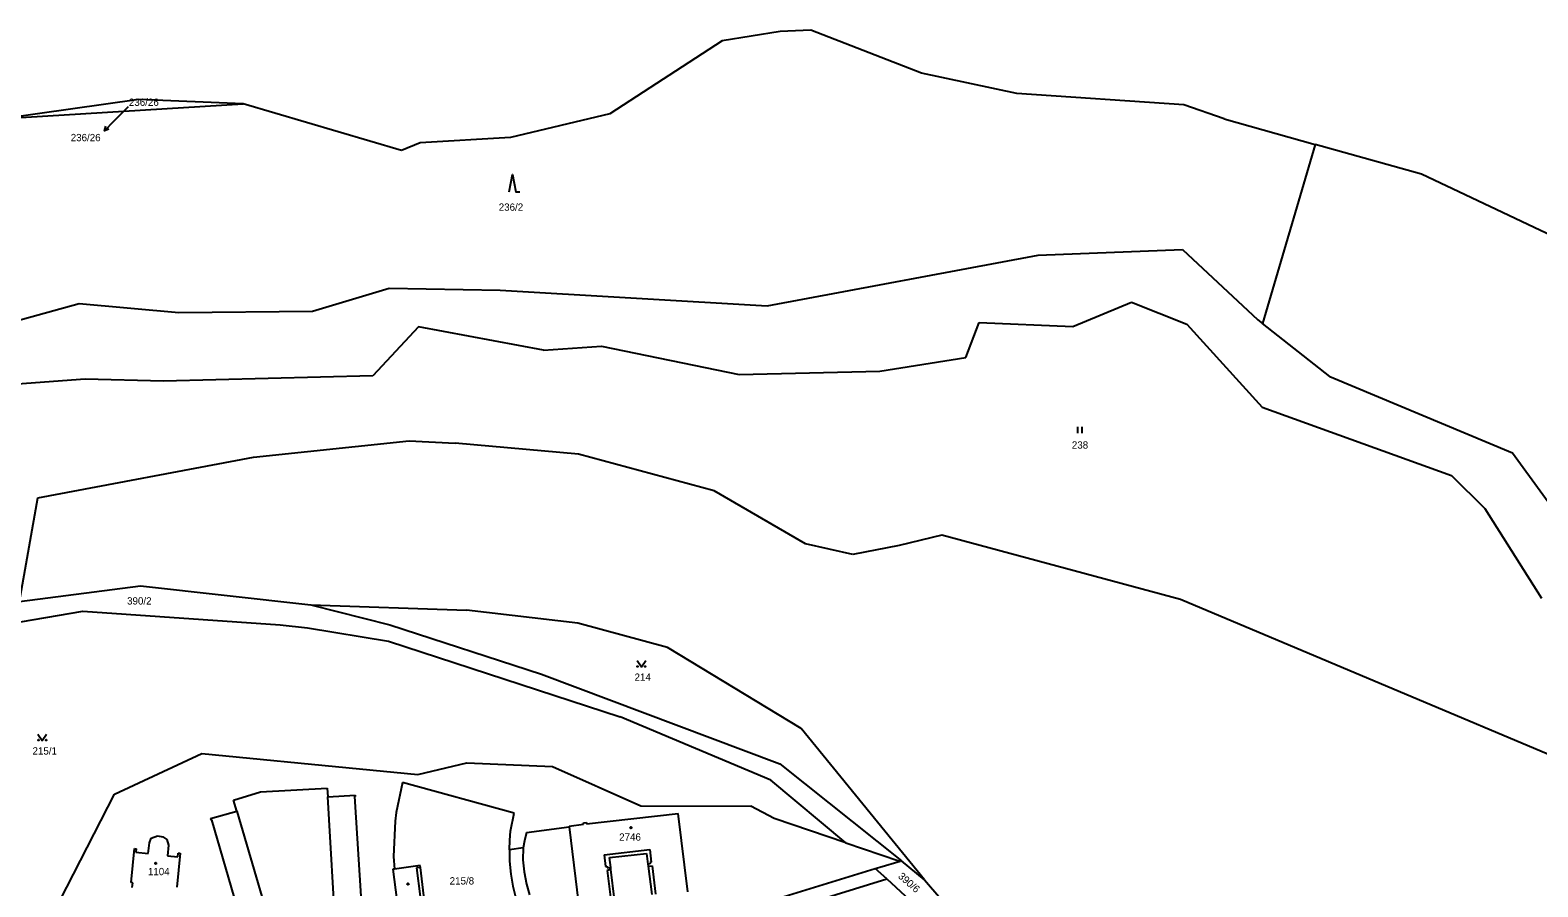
# Model space of a CAD drawing. Extents: x -735249 to -729401, y -1124843 to -1121828.
# Drawn here: x -733183.2 to -732832.6, y -1123120 to -1122920.8 of the extents above; entities that cross this region are included whole.
import ezdxf

# ---------------------------------------------------------------- set-up
doc = ezdxf.new("R2010")
doc.units = 0
for name, color, linetype in [('Vrstva 1', 7, 'Continuous'), ('Vrstva 13', 7, 'Continuous'), ('Vrstva 16', 7, 'Continuous'), ('Vrstva 18', 7, 'Continuous'), ('Vrstva 19', 7, 'Continuous'), ('Vrstva 25', 7, 'Continuous'), ('Vrstva 4', 7, 'Continuous')]:
    doc.layers.add(name, color=color, linetype=linetype)

msp = doc.modelspace()

# ---------------------------------------------------------------- linework, layer by layer
at = {"layer": 'Vrstva 1'}
for points in [[(-733189.11, -1122941.34), (-733133.6, -1122937.93)], [(-732884.33, -1122947.37), (-732896.64, -1122989.01)], [(-732948.78, -1122973.13), (-732915.22, -1122971.84)], [(-732915.22, -1122971.84), (-732897.69, -1122988.19)], [(-733011.81, -1122984.95), (-732948.78, -1122973.13)], [(-733117.5, -1122986.15), (-733099.68, -1122980.84)], [(-733099.68, -1122980.84), (-733073.84, -1122981.26)], [(-733073.84, -1122981.26), (-733011.81, -1122984.95)], [(-733196.77, -1122991.3), (-733171.8, -1122984.4)], [(-733171.8, -1122984.4), (-733148.57, -1122986.49)], [(-733148.57, -1122986.49), (-733117.5, -1122986.15)], [(-732940.73, -1122989.73), (-732927.06, -1122984.09)], [(-732927.06, -1122984.09), (-732914.22, -1122989.21)], [(-733092.85, -1122989.79), (-733103.46, -1123001.22)], [(-733063.77, -1122995.26), (-733092.85, -1122989.79)], [(-732965.57, -1122996.96), (-732962.49, -1122988.81)], [(-732962.49, -1122988.81), (-732940.73, -1122989.73)], [(-732914.22, -1122989.21), (-732896.65, -1123008.47)], [(-732897.69, -1122988.19), (-732896.64, -1122989.01)], [(-732880.92, -1123001.36), (-732896.64, -1122989.01)], [(-733063.77, -1122995.26), (-733050.28, -1122994.29)], [(-733050.28, -1122994.29), (-733018.28, -1123000.89)], [(-732985.6, -1123000.09), (-732965.57, -1122996.96)], [(-733018.28, -1123000.89), (-732985.6, -1123000.09)], [(-733170.37, -1123001.95), (-733190.38, -1123003.43)], [(-733152.15, -1123002.42), (-733170.37, -1123001.95)], [(-733103.46, -1123001.22), (-733152.15, -1123002.42)], [(-732880.92, -1123001.36), (-732838.49, -1123019.06)], [(-732896.65, -1123008.47), (-732852.64, -1123024.38)], [(-733131.23, -1123020.12), (-733095.01, -1123016.34)], [(-733095.01, -1123016.34), (-733084.33, -1123016.85)], [(-733055.66, -1123019.42), (-733084.33, -1123016.85)], [(-733181.36, -1123029.55), (-733131.23, -1123020.12)], [(-733024.13, -1123027.9), (-733055.66, -1123019.42)], [(-732838.49, -1123019.06), (-732817.96, -1123047.33)], [(-732852.64, -1123024.38), (-732844.88, -1123032.05)], [(-733002.9, -1123040.26), (-733024.13, -1123027.9)], [(-733185.61, -1123053.69), (-733181.36, -1123029.55)], [(-732844.88, -1123032.05), (-732831.71, -1123052.91)], [(-732971.16, -1123038.2), (-732981.06, -1123040.67)], [(-732915.67, -1123053.17), (-732971.16, -1123038.2)], [(-732991.84, -1123042.7), (-733002.9, -1123040.26)], [(-732981.06, -1123040.67), (-732991.84, -1123042.7)], [(-733185.61, -1123053.69), (-733157.54, -1123050.02)], [(-733157.54, -1123050.02), (-733117.91, -1123054.44)], [(-732776.55, -1123111.77), (-732915.67, -1123053.17)], [(-733196.82, -1123060.33), (-733170.92, -1123055.92)], [(-733170.92, -1123055.92), (-733125, -1123059.07)], [(-733117.91, -1123054.44), (-733081.67, -1123055.68)], [(-733117.91, -1123054.44), (-733099.52, -1123059.12)], [(-733055.81, -1123058.66), (-733081.67, -1123055.68)], [(-733125, -1123059.07), (-733118.7, -1123059.82)], [(-733118.7, -1123059.82), (-733099.83, -1123062.89)], [(-733099.52, -1123059.12), (-733064.28, -1123070.55)], [(-733034.93, -1123064.35), (-733055.81, -1123058.66)], [(-733099.83, -1123062.89), (-733045.98, -1123080.5)], [(-733003.86, -1123083.15), (-733034.93, -1123064.35)], [(-733064.28, -1123070.55), (-733008.85, -1123091.44)], [(-733010.91, -1123095.2), (-733045.98, -1123080.5)], [(-732975.22, -1123118.38), (-733003.86, -1123083.15)], [(-733163.54, -1123098.49), (-733143.24, -1123088.98)], [(-733143.24, -1123088.98), (-733106.62, -1123092.53)], [(-733093.03, -1123093.89), (-733081.63, -1123091.2)], [(-733081.63, -1123091.2), (-733061.72, -1123092.03)], [(-733061.72, -1123092.03), (-733041.19, -1123101.14)], [(-733008.85, -1123091.44), (-732980.57, -1123113.98)], [(-733106.62, -1123092.53), (-733093.03, -1123093.89)], [(-732993.5, -1123109.8), (-733010.91, -1123095.2)], [(-733177.79, -1123126.27), (-733163.54, -1123098.49)], [(-733135.87, -1123099.84), (-733129.57, -1123097.94)], [(-733129.57, -1123097.94), (-733114.09, -1123097.06)], [(-733114.09, -1123097.06), (-733113.97, -1123099.06)], [(-733113.97, -1123099.06), (-733107.58, -1123098.68)], [(-733107.56, -1123098.98), (-733107.72, -1123098.99)], [(-733107.72, -1123098.99), (-733105.68, -1123131.95)], [(-733107.58, -1123098.68), (-733107.56, -1123098.98)], [(-733096.62, -1123095.71), (-733098.05, -1123102.75)], [(-733070.61, -1123102.85), (-733096.62, -1123095.71)], [(-733141.25, -1123104.12), (-733135.13, -1123102.38)], [(-733135.13, -1123102.38), (-733135.87, -1123099.84)], [(-733041.19, -1123101.14), (-733015.6, -1123101.24)], [(-733010.19, -1123104.15), (-733015.6, -1123101.24)], [(-733141.25, -1123104.12), (-733141.16, -1123104.43)], [(-733141.16, -1123104.43), (-733141.02, -1123104.39)], [(-733141.02, -1123104.39), (-733132.54, -1123133.48)], [(-733098.33, -1123104.72), (-733098.71, -1123112.94)], [(-733098.05, -1123102.75), (-733098.33, -1123104.72)], [(-733071.45, -1123107.08), (-733070.61, -1123102.85)], [(-733067.73, -1123107.33), (-733057.83, -1123106.07)], [(-733057.85, -1123105.86), (-733054.46, -1123105.44)], [(-733057.85, -1123105.86), (-733057.83, -1123106.07)], [(-733057.83, -1123106.07), (-733055.66, -1123123.85)], [(-733054.48, -1123105.13), (-733053.83, -1123105.08)], [(-733054.46, -1123105.44), (-733054.48, -1123105.13)], [(-733053.83, -1123105.08), (-733053.81, -1123105.39)], [(-733053.81, -1123105.39), (-733032.49, -1123102.93)], [(-733030.21, -1123121.19), (-733032.49, -1123102.93)], [(-732993.5, -1123109.8), (-733010.19, -1123104.15)], [(-733155.45, -1123109.75), (-733155.03, -1123108.69)], [(-733155.03, -1123108.69), (-733153.55, -1123108.12)], [(-733153.55, -1123108.12), (-733152.35, -1123108.36)], [(-733152.35, -1123108.36), (-733151.39, -1123109.03)], [(-733151.39, -1123109.03), (-733150.97, -1123110.31)], [(-733071.72, -1123111.4), (-733071.6, -1123109.15)], [(-733071.6, -1123109.15), (-733071.45, -1123107.08)], [(-733068.21, -1123109.28), (-733068.49, -1123110.95)], [(-733067.73, -1123107.33), (-733068.21, -1123109.28)], [(-733159.71, -1123119.03), (-733158.92, -1123111.09)], [(-733158.92, -1123111.09), (-733158.51, -1123111.14)], [(-733158.51, -1123111.14), (-733158.59, -1123111.92)], [(-733158.59, -1123111.92), (-733155.75, -1123112.23)], [(-733155.75, -1123112.23), (-733155.45, -1123109.75)], [(-733150.97, -1123110.31), (-733151.23, -1123112.76)], [(-733151.23, -1123112.76), (-733148.85, -1123113)], [(-733148.3, -1123112.17), (-733149.08, -1123120.11)], [(-733148.85, -1123113), (-733148.72, -1123112.21)], [(-733148.72, -1123112.21), (-733148.3, -1123112.17)], [(-733098.71, -1123112.94), (-733098.47, -1123115.87)], [(-733068.49, -1123110.95), (-733071.72, -1123111.4)], [(-733048.45, -1123113.21), (-733039.82, -1123112.24)], [(-733039.82, -1123112.24), (-733039.52, -1123114.71)], [(-732993.5, -1123109.8), (-732981.15, -1123113.99)], [(-733098.47, -1123115.87), (-733098.8, -1123115.93)], [(-733098.8, -1123115.93), (-733097.24, -1123128.54)], [(-733092.49, -1123115.01), (-733098.47, -1123115.87)], [(-733092.43, -1123115.48), (-733092.49, -1123115.01)], [(-733091.63, -1123122.07), (-733092.43, -1123115.48)], [(-733048.18, -1123115.51), (-733048.45, -1123113.21)], [(-733048.12, -1123116), (-733048.18, -1123115.51)], [(-733047.27, -1123122.96), (-733048.12, -1123116)], [(-733039.52, -1123114.71), (-733039.48, -1123115.19)], [(-733039.48, -1123115.19), (-733038.62, -1123121.77)], [(-733035.05, -1123130.65), (-732986.71, -1123115.74)], [(-732986.71, -1123115.74), (-732985.57, -1123115.4)], [(-732983.98, -1123118.16), (-732986.71, -1123115.74)], [(-732985.57, -1123115.4), (-732980.9, -1123114.07)], [(-732981.15, -1123113.99), (-732980.9, -1123114.07)], [(-732980.57, -1123113.98), (-732980.9, -1123114.07)], [(-732975.22, -1123118.38), (-732980.57, -1123113.98)], [(-733159.32, -1123119.07), (-733159.71, -1123119.03)], [(-733159.44, -1123120.18), (-733159.32, -1123119.07)], [(-733140.36, -1123166.52), (-732983.98, -1123118.16)], [(-732983.98, -1123118.16), (-732978.66, -1123123.04)], [(-732975.22, -1123118.38), (-732956.7, -1123139.95)]]:
    msp.add_lwpolyline(points, dxfattribs=at)
at = {"layer": 'Vrstva 13'}
for points in [[(-733022.26, -1122923.27), (-733048.34, -1122940.27)], [(-733008.79, -1122921.12), (-733022.26, -1122923.27)], [(-733001.61, -1122920.82), (-733008.79, -1122921.12)], [(-732975.9, -1122930.79), (-733001.61, -1122920.82)], [(-732953.74, -1122935.53), (-732975.9, -1122930.79)], [(-733157.87, -1122936.95), (-733189.11, -1122941.34)], [(-733133.6, -1122937.93), (-733157.87, -1122936.95)], [(-732914.88, -1122938.18), (-732953.74, -1122935.53)], [(-733096.81, -1122948.81), (-733133.6, -1122937.93)], [(-733048.34, -1122940.27), (-733071.46, -1122945.74)], [(-732905.5, -1122941.4), (-732914.88, -1122938.18)], [(-732905.5, -1122941.4), (-732884.33, -1122947.37)], [(-733092.47, -1122947), (-733096.81, -1122948.81)], [(-733071.46, -1122945.74), (-733092.47, -1122947)], [(-732859.61, -1122954.34), (-732884.33, -1122947.37)], [(-732794.28, -1122985.24), (-732859.61, -1122954.34)]]:
    msp.add_lwpolyline(points, dxfattribs=at)
at = {"layer": 'Vrstva 16'}
msp.add_lwpolyline([(-733160.41, -1122938.62), (-733163.8, -1122942.09)], dxfattribs=at)
at = {"layer": 'Vrstva 25'}
for points in [[(-733163.8, -1122942.09), (-733165.898, -1122944.233)], [(-733164.842, -1122943.868), (-733165.898, -1122944.233), (-733165.556, -1122943.169)], [(-733071.77, -1122958.41), (-733071.02, -1122954.41), (-733070.27, -1122958.41), (-733069.27, -1122958.41)], [(-732939.557, -1123014.545), (-732939.557, -1123013.045)], [(-732938.523, -1123014.545), (-732938.523, -1123013.045)], [(-733042.04, -1123067.36), (-733041.04, -1123068.86), (-733040.04, -1123067.36)], [(-733181.35, -1123084.47), (-733180.35, -1123085.97), (-733179.35, -1123084.47)]]:
    msp.add_lwpolyline(points, dxfattribs=at)
for centre, radius in [((-733041.94, -1123068.76), 0.1), ((-733040.14, -1123068.76), 0.1), ((-733181.25, -1123085.87), 0.1), ((-733179.45, -1123085.87), 0.1), ((-733043.48, -1123106.24), 0.175), ((-733153.96, -1123114.53), 0.175), ((-733095.31, -1123119.34), 0.175)]:
    msp.add_circle(centre, radius, dxfattribs=at)
at = {"layer": 'Vrstva 4'}
for points in [[(-733112, -1123132.26), (-733113.97, -1123099.06)], [(-733135.13, -1123102.38), (-733126.14, -1123133.12)], [(-733071.72, -1123111.4), (-733071.68, -1123114)], [(-733068.49, -1123110.95), (-733068.57, -1123113.69)], [(-733049.73, -1123112.53), (-733039.06, -1123111.29)], [(-733049.73, -1123112.53), (-733049.41, -1123115.26)], [(-733039.06, -1123111.29), (-733038.74, -1123114.29)], [(-733092.43, -1123115.48), (-733093.33, -1123115.62)], [(-733093.33, -1123115.62), (-733092.47, -1123122.25)], [(-733071.68, -1123114), (-733071.42, -1123117.08)], [(-733068.57, -1123113.69), (-733068.26, -1123116.54)], [(-733068.26, -1123116.54), (-733067.75, -1123119.37)], [(-733049.41, -1123115.26), (-733049.03, -1123115.22)], [(-733049.03, -1123115.22), (-733048.98, -1123115.61)], [(-733048.98, -1123115.61), (-733048.18, -1123115.51)], [(-733048.12, -1123116), (-733048.98, -1123116.19)], [(-733048.98, -1123116.19), (-733048.14, -1123123.06)], [(-733039.02, -1123114.65), (-733039.52, -1123114.71)], [(-733039.48, -1123115.19), (-733038.57, -1123115.1)], [(-733038.74, -1123114.29), (-733039.06, -1123114.33)], [(-733039.06, -1123114.33), (-733039.02, -1123114.65)], [(-733038.57, -1123115.1), (-733037.72, -1123121.67)], [(-733071.42, -1123117.08), (-733070.92, -1123119.88)], [(-733070.92, -1123119.88), (-733070.34, -1123122.32)], [(-733067.75, -1123119.37), (-733067.05, -1123121.87)]]:
    msp.add_lwpolyline(points, dxfattribs=at)

# ---------------------------------------------------------------- texts
at = {"layer": 'Vrstva 16'}
msp.add_text('236/26', height=1.7, dxfattribs=at).set_placement((-733173.737, -1122946.64))
at = {"layer": 'Vrstva 18'}
for s, p in [('236/26', (-733160.21, -1122938.42)), ('236/2', (-733074.21, -1122962.81)), ('238', (-732940.94, -1123018.12)), ('390/2', (-733160.63, -1123054.37)), ('214', (-733042.63, -1123072.1)), ('215/1', (-733182.62, -1123089.25)), ('215/8', (-733085.62, -1123119.46))]:
    msp.add_text(s, height=1.7, dxfattribs=at).set_placement(p)
msp.add_text('390/6', height=1.7, rotation=318.60253, dxfattribs=at).set_placement((-732981.478, -1123117.753))
at = {"layer": 'Vrstva 19'}
for s, p in [('2746', (-733046.21, -1123109.27)), ('1104', (-733155.79, -1123117.3))]:
    msp.add_text(s, height=1.7, dxfattribs=at).set_placement(p)

doc.saveas('drawing.dxf')
